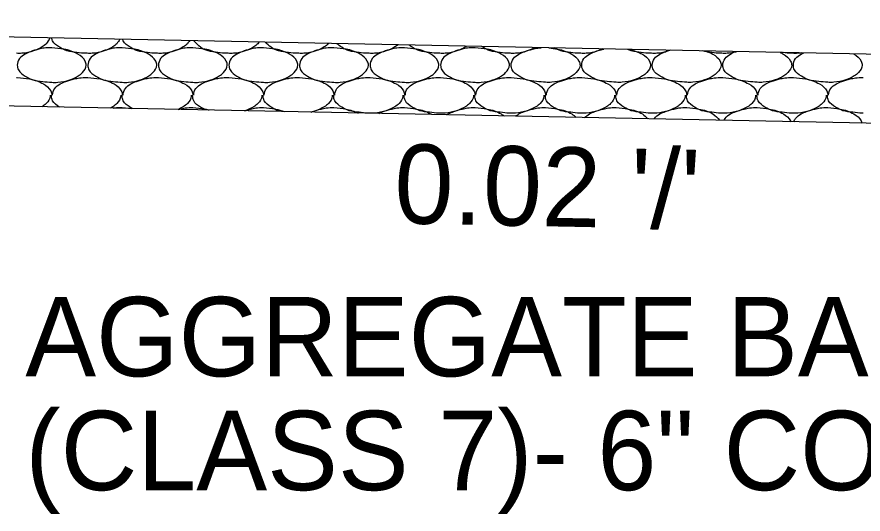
# Model space of a CAD drawing. Extents: x 1364961 to 1365294, y 367927 to 368034.
# Drawn here: x 1365039.35 to 1365045.49, y 367994.83 to 367998.44 of the extents above; entities that cross this region are included whole.
import ezdxf

# ---------------------------------------------------------------- set-up
doc = ezdxf.new("R2010")
doc.units = 0
doc.layers.add('Default', color=7, linetype='Continuous')

msp = doc.modelspace()

# ---------------------------------------------------------------- linework, layer by layer
at = {"layer": 'Default'}
for p, q in [((1365055.9752, 367997.9597), (1365031.9883, 367998.4397)), ((1365039.3502, 367997.9997), (1365039.3562, 367997.9997)), ((1365039.8622, 367997.9997), (1365039.8682, 367997.9997)), ((1365040.3742, 367997.9997), (1365040.3802, 367997.9997)), ((1365040.8862, 367997.9997), (1365040.8922, 367997.9997)), ((1365041.3982, 367997.9997), (1365041.4042, 367997.9997)), ((1365041.9102, 367997.9997), (1365041.9162, 367997.9997)), ((1365042.4222, 367997.9997), (1365042.4282, 367997.9997)), ((1365042.9342, 367997.9997), (1365042.9402, 367997.9997)), ((1365043.4462, 367997.9997), (1365043.4522, 367997.9997)), ((1365043.9582, 367997.9997), (1365043.9642, 367997.9997)), ((1365044.4702, 367997.9997), (1365044.4762, 367997.9997)), ((1365044.9822, 367997.9997), (1365044.9882, 367997.9997)), ((1365055.9752, 367997.4597), (1365031.9783, 367997.9397)), ((1365040.1182, 367997.7817), (1365040.1862, 367997.7757))]:
    msp.add_line(p, q, dxfattribs=at)
for points in [[(1365039.5922, 367998.2877), (1365039.5662, 367998.2457), (1365039.5362, 367998.2217), (1365039.4742, 367998.1937), (1365039.3882, 367998.1757), (1365039.3502, 367998.1757)], [(1365039.8622, 367998.1757), (1365039.8542, 367998.1757), (1365039.7882, 367998.1817), (1365039.7162, 367998.1937), (1365039.6622, 367998.2197), (1365039.6122, 367998.2657), (1365039.6052, 367998.2877)], [(1365040.1002, 367998.2777), (1365040.0782, 367998.2457), (1365040.0482, 367998.2217), (1365039.9862, 367998.1937), (1365039.9002, 367998.1757), (1365039.8622, 367998.1757)], [(1365040.3742, 367998.1757), (1365040.3662, 367998.1757), (1365040.3002, 367998.1817), (1365040.2282, 367998.1937), (1365040.1742, 367998.2197), (1365040.1242, 367998.2657), (1365040.1192, 367998.2767)], [(1365040.6072, 367998.2677), (1365040.5902, 367998.2457), (1365040.5602, 367998.2217), (1365040.4982, 367998.1937), (1365040.4122, 367998.1757), (1365040.3742, 367998.1757)], [(1365040.8862, 367998.1757), (1365040.8782, 367998.1757), (1365040.8122, 367998.1817), (1365040.7402, 367998.1937), (1365040.6862, 367998.2197), (1365040.6362, 367998.2657), (1365040.6352, 367998.2667)], [(1365041.1122, 367998.2567), (1365041.1022, 367998.2457), (1365041.0722, 367998.2217), (1365041.0102, 367998.1937), (1365040.9242, 367998.1757), (1365040.8862, 367998.1757)], [(1365041.3982, 367998.1757), (1365041.3902, 367998.1757), (1365041.3242, 367998.1817), (1365041.2522, 367998.1937), (1365041.1982, 367998.2197), (1365041.1542, 367998.2567)], [(1365041.6152, 367998.2467), (1365041.6142, 367998.2457), (1365041.5842, 367998.2217), (1365041.5222, 367998.1937), (1365041.4362, 367998.1757), (1365041.3982, 367998.1757)], [(1365041.9102, 367998.1757), (1365041.9022, 367998.1757), (1365041.8362, 367998.1817), (1365041.7642, 367998.1937), (1365041.7102, 367998.2197), (1365041.6752, 367998.2457)], [(1365042.1172, 367998.2367), (1365042.0962, 367998.2217), (1365042.0342, 367998.1937), (1365041.9482, 367998.1757), (1365041.9102, 367998.1757)], [(1365039.6062, 367998.2157), (1365039.6942, 367998.2057), (1365039.7962, 367998.1697), (1365039.8482, 367998.1197), (1365039.8562, 367998.0897), (1365039.8282, 367998.0357), (1365039.7982, 367998.0117), (1365039.7362, 367997.9837), (1365039.6502, 367997.9657), (1365039.6062, 367997.9657), (1365039.5402, 367997.9717), (1365039.4682, 367997.9837), (1365039.4142, 367998.0097), (1365039.3642, 367998.0557), (1365039.3562, 367998.0897), (1365039.3722, 367998.1377), (1365039.4122, 367998.1697), (1365039.4522, 367998.1877), (1365039.5122, 367998.2057), (1365039.5502, 367998.2137), (1365039.6062, 367998.2157)], [(1365040.1182, 367998.2157), (1365040.2062, 367998.2057), (1365040.3082, 367998.1697), (1365040.3602, 367998.1197), (1365040.3682, 367998.0897), (1365040.3402, 367998.0357), (1365040.3102, 367998.0117), (1365040.2482, 367997.9837), (1365040.1622, 367997.9657), (1365040.1182, 367997.9657), (1365040.0522, 367997.9717), (1365039.9802, 367997.9837), (1365039.9262, 367998.0097), (1365039.8762, 367998.0557), (1365039.8682, 367998.0897), (1365039.8842, 367998.1377), (1365039.9242, 367998.1697), (1365039.9642, 367998.1877), (1365040.0242, 367998.2057), (1365040.0622, 367998.2137), (1365040.1182, 367998.2157)], [(1365040.6302, 367998.2157), (1365040.7182, 367998.2057), (1365040.8202, 367998.1697), (1365040.8722, 367998.1197), (1365040.8802, 367998.0897), (1365040.8522, 367998.0357), (1365040.8222, 367998.0117), (1365040.7602, 367997.9837), (1365040.6742, 367997.9657), (1365040.6302, 367997.9657), (1365040.5642, 367997.9717), (1365040.4922, 367997.9837), (1365040.4382, 367998.0097), (1365040.3882, 367998.0557), (1365040.3802, 367998.0897), (1365040.3962, 367998.1377), (1365040.4362, 367998.1697), (1365040.4762, 367998.1877), (1365040.5362, 367998.2057), (1365040.5742, 367998.2137), (1365040.6302, 367998.2157)], [(1365041.1422, 367998.2157), (1365041.2302, 367998.2057), (1365041.3322, 367998.1697), (1365041.3842, 367998.1197), (1365041.3922, 367998.0897), (1365041.3642, 367998.0357), (1365041.3342, 367998.0117), (1365041.2722, 367997.9837), (1365041.1862, 367997.9657), (1365041.1422, 367997.9657), (1365041.0762, 367997.9717), (1365041.0042, 367997.9837), (1365040.9502, 367998.0097), (1365040.9002, 367998.0557), (1365040.8922, 367998.0897), (1365040.9082, 367998.1377), (1365040.9482, 367998.1697), (1365040.9882, 367998.1877), (1365041.0482, 367998.2057), (1365041.0862, 367998.2137), (1365041.1422, 367998.2157)], [(1365041.6542, 367998.2157), (1365041.7422, 367998.2057), (1365041.8442, 367998.1697), (1365041.8962, 367998.1197), (1365041.9042, 367998.0897), (1365041.8762, 367998.0357), (1365041.8462, 367998.0117), (1365041.7842, 367997.9837), (1365041.6982, 367997.9657), (1365041.6542, 367997.9657), (1365041.5882, 367997.9717), (1365041.5162, 367997.9837), (1365041.4622, 367998.0097), (1365041.4122, 367998.0557), (1365041.4042, 367998.0897), (1365041.4202, 367998.1377), (1365041.4602, 367998.1697), (1365041.5002, 367998.1877), (1365041.5602, 367998.2057), (1365041.5982, 367998.2137), (1365041.6542, 367998.2157)], [(1365042.1662, 367998.2157), (1365042.2542, 367998.2057), (1365042.3562, 367998.1697), (1365042.4082, 367998.1197), (1365042.4162, 367998.0897), (1365042.3882, 367998.0357), (1365042.3582, 367998.0117), (1365042.2962, 367997.9837), (1365042.2102, 367997.9657), (1365042.1662, 367997.9657), (1365042.1002, 367997.9717), (1365042.0282, 367997.9837), (1365041.9742, 367998.0097), (1365041.9242, 367998.0557), (1365041.9162, 367998.0897), (1365041.9322, 367998.1377), (1365041.9722, 367998.1697), (1365042.0122, 367998.1877), (1365042.0722, 367998.2057), (1365042.1102, 367998.2137), (1365042.1662, 367998.2157)], [(1365042.4222, 367998.1757), (1365042.4142, 367998.1757), (1365042.3482, 367998.1817), (1365042.2762, 367998.1937), (1365042.2222, 367998.2197), (1365042.1992, 367998.2357)], [(1365042.6172, 367998.2267), (1365042.6082, 367998.2217), (1365042.5462, 367998.1937), (1365042.4602, 367998.1757), (1365042.4222, 367998.1757)], [(1365042.6782, 367998.2157), (1365042.7662, 367998.2057), (1365042.8682, 367998.1697), (1365042.9202, 367998.1197), (1365042.9282, 367998.0897), (1365042.9002, 367998.0357), (1365042.8702, 367998.0117), (1365042.8082, 367997.9837), (1365042.7222, 367997.9657), (1365042.6782, 367997.9657), (1365042.6122, 367997.9717), (1365042.5402, 367997.9837), (1365042.4862, 367998.0097), (1365042.4362, 367998.0557), (1365042.4282, 367998.0897), (1365042.4442, 367998.1377), (1365042.4842, 367998.1697), (1365042.5242, 367998.1877), (1365042.5842, 367998.2057), (1365042.6222, 367998.2137), (1365042.6782, 367998.2157)], [(1365042.9342, 367998.1757), (1365042.9262, 367998.1757), (1365042.8602, 367998.1817), (1365042.7882, 367998.1937), (1365042.7342, 367998.2197), (1365042.7262, 367998.2247)], [(1365043.1122, 367998.2167), (1365043.0582, 367998.1937), (1365042.9722, 367998.1757), (1365042.9342, 367998.1757)], [(1365043.2132, 367998.2147), (1365043.2782, 367998.2057), (1365043.3802, 367998.1697), (1365043.4322, 367998.1197), (1365043.4402, 367998.0897), (1365043.4122, 367998.0357), (1365043.3822, 367998.0117), (1365043.3202, 367997.9837), (1365043.2342, 367997.9657), (1365043.1902, 367997.9657), (1365043.1242, 367997.9717), (1365043.0522, 367997.9837), (1365042.9982, 367998.0097), (1365042.9482, 367998.0557), (1365042.9402, 367998.0897), (1365042.9562, 367998.1377), (1365042.9962, 367998.1697), (1365043.0362, 367998.1877), (1365043.0962, 367998.2057), (1365043.1342, 367998.2137), (1365043.1582, 367998.2157)], [(1365043.4462, 367998.1757), (1365043.4382, 367998.1757), (1365043.3722, 367998.1817), (1365043.3002, 367998.1937), (1365043.2552, 367998.2147)], [(1365043.6042, 367998.2077), (1365043.5702, 367998.1937), (1365043.4842, 367998.1757), (1365043.4462, 367998.1757)], [(1365043.8012, 367998.2037), (1365043.8922, 367998.1697), (1365043.9442, 367998.1197), (1365043.9522, 367998.0897), (1365043.9242, 367998.0357), (1365043.8942, 367998.0117), (1365043.8322, 367997.9837), (1365043.7462, 367997.9657), (1365043.7022, 367997.9657), (1365043.6362, 367997.9717), (1365043.5642, 367997.9837), (1365043.5102, 367998.0097), (1365043.4602, 367998.0557), (1365043.4522, 367998.0897), (1365043.4682, 367998.1377), (1365043.5082, 367998.1697), (1365043.5482, 367998.1877), (1365043.6082, 367998.2057), (1365043.6132, 367998.2067)], [(1365043.9582, 367998.1757), (1365043.9502, 367998.1757), (1365043.8842, 367998.1817), (1365043.8122, 367998.1937), (1365043.7862, 367998.2037)], [(1365044.0932, 367998.1977), (1365044.0822, 367998.1937), (1365043.9962, 367998.1757), (1365043.9582, 367998.1757)], [(1365044.3522, 367998.1927), (1365044.4042, 367998.1697), (1365044.4562, 367998.1197), (1365044.4642, 367998.0897), (1365044.4362, 367998.0357), (1365044.4062, 367998.0117), (1365044.3442, 367997.9837), (1365044.2582, 367997.9657), (1365044.2142, 367997.9657), (1365044.1482, 367997.9717), (1365044.0762, 367997.9837), (1365044.0222, 367998.0097), (1365043.9722, 367998.0557), (1365043.9642, 367998.0897), (1365043.9802, 367998.1377), (1365044.0202, 367998.1697), (1365044.0602, 367998.1877), (1365044.0912, 367998.1977)], [(1365044.4702, 367998.1757), (1365044.4622, 367998.1757), (1365044.3962, 367998.1817), (1365044.3282, 367998.1927)], [(1365044.5752, 367998.1877), (1365044.5082, 367998.1757), (1365044.4702, 367998.1757)], [(1365044.8922, 367998.1817), (1365044.9162, 367998.1697), (1365044.9682, 367998.1197), (1365044.9762, 367998.0897), (1365044.9482, 367998.0357), (1365044.9182, 367998.0117), (1365044.8562, 367997.9837), (1365044.7702, 367997.9657), (1365044.7262, 367997.9657), (1365044.6602, 367997.9717), (1365044.5882, 367997.9837), (1365044.5342, 367998.0097), (1365044.4842, 367998.0557), (1365044.4762, 367998.0897), (1365044.4922, 367998.1377), (1365044.5322, 367998.1697), (1365044.5722, 367998.1877), (1365044.5732, 367998.1877)], [(1365044.9822, 367998.1757), (1365044.9742, 367998.1757), (1365044.9142, 367998.1807)], [(1365045.0462, 367998.1787), (1365045.0202, 367998.1757), (1365044.9822, 367998.1757)], [(1365045.4262, 367998.1707), (1365045.4282, 367998.1697), (1365045.4802, 367998.1197), (1365045.4882, 367998.0897), (1365045.4602, 367998.0357), (1365045.4302, 367998.0117), (1365045.3682, 367997.9837), (1365045.2822, 367997.9657), (1365045.2382, 367997.9657), (1365045.1722, 367997.9717), (1365045.1002, 367997.9837), (1365045.0462, 367998.0097), (1365044.9962, 367998.0557), (1365044.9882, 367998.0897), (1365045.0042, 367998.1377), (1365045.0442, 367998.1697), (1365045.0612, 367998.1777)], [(1365039.3562, 367997.9997), (1365039.4442, 367997.9897), (1365039.5462, 367997.9537), (1365039.5982, 367997.9037), (1365039.6062, 367997.8737), (1365039.6062, 367997.8717)], [(1365039.6122, 367997.8717), (1365039.6122, 367997.8737), (1365039.6282, 367997.9217), (1365039.6682, 367997.9537), (1365039.7082, 367997.9717), (1365039.7682, 367997.9897), (1365039.8062, 367997.9977), (1365039.8622, 367997.9997)], [(1365039.8682, 367997.9997), (1365039.9562, 367997.9897), (1365040.0582, 367997.9537), (1365040.1102, 367997.9037), (1365040.1182, 367997.8737), (1365040.1182, 367997.8717)], [(1365040.1242, 367997.8717), (1365040.1242, 367997.8737), (1365040.1402, 367997.9217), (1365040.1802, 367997.9537), (1365040.2202, 367997.9717), (1365040.2802, 367997.9897), (1365040.3182, 367997.9977), (1365040.3742, 367997.9997)], [(1365040.3802, 367997.9997), (1365040.4682, 367997.9897), (1365040.5702, 367997.9537), (1365040.6222, 367997.9037), (1365040.6302, 367997.8737), (1365040.6302, 367997.8717)], [(1365040.6362, 367997.8717), (1365040.6362, 367997.8737), (1365040.6522, 367997.9217), (1365040.6922, 367997.9537), (1365040.7322, 367997.9717), (1365040.7922, 367997.9897), (1365040.8302, 367997.9977), (1365040.8862, 367997.9997)], [(1365040.8922, 367997.9997), (1365040.9802, 367997.9897), (1365041.0822, 367997.9537), (1365041.1342, 367997.9037), (1365041.1422, 367997.8737), (1365041.1422, 367997.8717)], [(1365041.1482, 367997.8717), (1365041.1482, 367997.8737), (1365041.1642, 367997.9217), (1365041.2042, 367997.9537), (1365041.2442, 367997.9717), (1365041.3042, 367997.9897), (1365041.3422, 367997.9977), (1365041.3982, 367997.9997)], [(1365041.4042, 367997.9997), (1365041.4922, 367997.9897), (1365041.5942, 367997.9537), (1365041.6462, 367997.9037), (1365041.6542, 367997.8737), (1365041.6542, 367997.8717)], [(1365041.6602, 367997.8717), (1365041.6602, 367997.8737), (1365041.6762, 367997.9217), (1365041.7162, 367997.9537), (1365041.7562, 367997.9717), (1365041.8162, 367997.9897), (1365041.8542, 367997.9977), (1365041.9102, 367997.9997)], [(1365041.9162, 367997.9997), (1365042.0042, 367997.9897), (1365042.1062, 367997.9537), (1365042.1582, 367997.9037), (1365042.1662, 367997.8737), (1365042.1662, 367997.8717)], [(1365042.1722, 367997.8717), (1365042.1722, 367997.8737), (1365042.1882, 367997.9217), (1365042.2282, 367997.9537), (1365042.2682, 367997.9717), (1365042.3282, 367997.9897), (1365042.3662, 367997.9977), (1365042.4222, 367997.9997)], [(1365042.4282, 367997.9997), (1365042.5162, 367997.9897), (1365042.6182, 367997.9537), (1365042.6702, 367997.9037), (1365042.6782, 367997.8737), (1365042.6782, 367997.8717)], [(1365042.6842, 367997.8717), (1365042.6842, 367997.8737), (1365042.7002, 367997.9217), (1365042.7402, 367997.9537), (1365042.7802, 367997.9717), (1365042.8402, 367997.9897), (1365042.8782, 367997.9977), (1365042.9342, 367997.9997)], [(1365042.9402, 367997.9997), (1365043.0282, 367997.9897), (1365043.1302, 367997.9537), (1365043.1822, 367997.9037), (1365043.1902, 367997.8737), (1365043.1902, 367997.8717)], [(1365043.1962, 367997.8717), (1365043.1962, 367997.8737), (1365043.2122, 367997.9217), (1365043.2522, 367997.9537), (1365043.2922, 367997.9717), (1365043.3522, 367997.9897), (1365043.3902, 367997.9977), (1365043.4462, 367997.9997)], [(1365043.4522, 367997.9997), (1365043.5402, 367997.9897), (1365043.6422, 367997.9537), (1365043.6942, 367997.9037), (1365043.7022, 367997.8737), (1365043.7022, 367997.8717)], [(1365043.7082, 367997.8717), (1365043.7082, 367997.8737), (1365043.7242, 367997.9217), (1365043.7642, 367997.9537), (1365043.8042, 367997.9717), (1365043.8642, 367997.9897), (1365043.9022, 367997.9977), (1365043.9582, 367997.9997)], [(1365043.9642, 367997.9997), (1365044.0522, 367997.9897), (1365044.1542, 367997.9537), (1365044.2062, 367997.9037), (1365044.2142, 367997.8737), (1365044.2142, 367997.8717)], [(1365044.2202, 367997.8717), (1365044.2202, 367997.8737), (1365044.2362, 367997.9217), (1365044.2762, 367997.9537), (1365044.3162, 367997.9717), (1365044.3762, 367997.9897), (1365044.4142, 367997.9977), (1365044.4702, 367997.9997)], [(1365044.4762, 367997.9997), (1365044.5642, 367997.9897), (1365044.6662, 367997.9537), (1365044.7182, 367997.9037), (1365044.7262, 367997.8737), (1365044.7262, 367997.8717)], [(1365044.7322, 367997.8717), (1365044.7322, 367997.8737), (1365044.7482, 367997.9217), (1365044.7882, 367997.9537), (1365044.8282, 367997.9717), (1365044.8882, 367997.9897), (1365044.9262, 367997.9977), (1365044.9822, 367997.9997)], [(1365044.9882, 367997.9997), (1365045.0762, 367997.9897), (1365045.1782, 367997.9537), (1365045.2302, 367997.9037), (1365045.2382, 367997.8737), (1365045.2382, 367997.8717)], [(1365045.2442, 367997.8717), (1365045.2442, 367997.8737), (1365045.2602, 367997.9217), (1365045.3002, 367997.9537), (1365045.3402, 367997.9717), (1365045.4002, 367997.9897), (1365045.4382, 367997.9977), (1365045.4942, 367997.9997)], [(1365039.5942, 367997.8717), (1365039.5942, 367997.8657), (1365039.5662, 367997.8117), (1365039.5372, 367997.7887)], [(1365039.6622, 367997.7857), (1365039.6122, 367997.8317), (1365039.6042, 367997.8657), (1365039.6042, 367997.8717)], [(1365040.1062, 367997.8717), (1365040.1062, 367997.8657), (1365040.0782, 367997.8117), (1365040.0482, 367997.7877), (1365040.0312, 367997.7787)], [(1365040.1912, 367997.7757), (1365040.1742, 367997.7857), (1365040.1242, 367997.8317), (1365040.1162, 367997.8657), (1365040.1162, 367997.8717)], [(1365040.6182, 367997.8717), (1365040.6182, 367997.8657), (1365040.5902, 367997.8117), (1365040.5602, 367997.7877), (1365040.5222, 367997.7687)], [(1365040.7242, 367997.7647), (1365040.6862, 367997.7857), (1365040.6362, 367997.8317), (1365040.6282, 367997.8657), (1365040.6282, 367997.8717)], [(1365041.1302, 367997.8717), (1365041.1302, 367997.8657), (1365041.1022, 367997.8117), (1365041.0722, 367997.7877), (1365041.0102, 367997.7597), (1365041.0082, 367997.7587)], [(1365041.2822, 367997.7537), (1365041.2522, 367997.7597), (1365041.1982, 367997.7857), (1365041.1482, 367997.8317), (1365041.1402, 367997.8657), (1365041.1402, 367997.8717)], [(1365041.6422, 367997.8717), (1365041.6422, 367997.8657), (1365041.6142, 367997.8117), (1365041.5842, 367997.7877), (1365041.5222, 367997.7597), (1365041.4872, 367997.7497)], [(1365041.9102, 367997.7417), (1365041.9022, 367997.7417), (1365041.8362, 367997.7477), (1365041.7642, 367997.7597), (1365041.7102, 367997.7857), (1365041.6602, 367997.8317), (1365041.6522, 367997.8657), (1365041.6522, 367997.8717)], [(1365042.1542, 367997.8717), (1365042.1542, 367997.8657), (1365042.1262, 367997.8117), (1365042.0962, 367997.7877), (1365042.0342, 367997.7597), (1365041.9482, 367997.7417), (1365041.9102, 367997.7417)], [(1365042.4222, 367997.7417), (1365042.4142, 367997.7417), (1365042.3482, 367997.7477), (1365042.2762, 367997.7597), (1365042.2222, 367997.7857), (1365042.1722, 367997.8317), (1365042.1642, 367997.8657), (1365042.1642, 367997.8717)], [(1365042.6662, 367997.8717), (1365042.6662, 367997.8657), (1365042.6382, 367997.8117), (1365042.6082, 367997.7877), (1365042.5462, 367997.7597), (1365042.4602, 367997.7417), (1365042.4222, 367997.7417)], [(1365042.9342, 367997.7417), (1365042.9262, 367997.7417), (1365042.8602, 367997.7477), (1365042.7882, 367997.7597), (1365042.7342, 367997.7857), (1365042.6842, 367997.8317), (1365042.6762, 367997.8657), (1365042.6762, 367997.8717)], [(1365043.1782, 367997.8717), (1365043.1782, 367997.8657), (1365043.1502, 367997.8117), (1365043.1202, 367997.7877), (1365043.0582, 367997.7597), (1365042.9722, 367997.7417), (1365042.9342, 367997.7417)], [(1365043.4462, 367997.7417), (1365043.4382, 367997.7417), (1365043.3722, 367997.7477), (1365043.3002, 367997.7597), (1365043.2462, 367997.7857), (1365043.1962, 367997.8317), (1365043.1882, 367997.8657), (1365043.1882, 367997.8717)], [(1365043.6902, 367997.8717), (1365043.6902, 367997.8657), (1365043.6622, 367997.8117), (1365043.6322, 367997.7877), (1365043.5702, 367997.7597), (1365043.4842, 367997.7417), (1365043.4462, 367997.7417)], [(1365043.9582, 367997.7417), (1365043.9502, 367997.7417), (1365043.8842, 367997.7477), (1365043.8122, 367997.7597), (1365043.7582, 367997.7857), (1365043.7082, 367997.8317), (1365043.7002, 367997.8657), (1365043.7002, 367997.8717)], [(1365044.2022, 367997.8717), (1365044.2022, 367997.8657), (1365044.1742, 367997.8117), (1365044.1442, 367997.7877), (1365044.0822, 367997.7597), (1365043.9962, 367997.7417), (1365043.9582, 367997.7417)], [(1365044.4702, 367997.7417), (1365044.4622, 367997.7417), (1365044.3962, 367997.7477), (1365044.3242, 367997.7597), (1365044.2702, 367997.7857), (1365044.2202, 367997.8317), (1365044.2122, 367997.8657), (1365044.2122, 367997.8717)], [(1365044.7142, 367997.8717), (1365044.7142, 367997.8657), (1365044.6862, 367997.8117), (1365044.6562, 367997.7877), (1365044.5942, 367997.7597), (1365044.5082, 367997.7417), (1365044.4702, 367997.7417)], [(1365044.9822, 367997.7417), (1365044.9742, 367997.7417), (1365044.9082, 367997.7477), (1365044.8362, 367997.7597), (1365044.7822, 367997.7857), (1365044.7322, 367997.8317), (1365044.7242, 367997.8657), (1365044.7242, 367997.8717)], [(1365045.2262, 367997.8717), (1365045.2262, 367997.8657), (1365045.1982, 367997.8117), (1365045.1682, 367997.7877), (1365045.1062, 367997.7597), (1365045.0202, 367997.7417), (1365044.9822, 367997.7417)], [(1365045.4942, 367997.7417), (1365045.4862, 367997.7417), (1365045.4202, 367997.7477), (1365045.3482, 367997.7597), (1365045.2942, 367997.7857), (1365045.2442, 367997.8317), (1365045.2362, 367997.8657), (1365045.2362, 367997.8717)], [(1365040.0532, 367997.7777), (1365040.0622, 367997.7797), (1365040.1182, 367997.7817)], [(1365040.5252, 367997.7687), (1365040.5362, 367997.7717), (1365040.5742, 367997.7797), (1365040.6302, 367997.7817)], [(1365040.6302, 367997.7817), (1365040.7182, 367997.7717), (1365040.7492, 367997.7647)], [(1365041.0052, 367997.7587), (1365041.0482, 367997.7717), (1365041.0862, 367997.7797), (1365041.1422, 367997.7817)], [(1365041.1422, 367997.7817), (1365041.2302, 367997.7717), (1365041.2942, 367997.7537)], [(1365041.4892, 367997.7497), (1365041.5002, 367997.7537), (1365041.5602, 367997.7717), (1365041.5982, 367997.7797), (1365041.6542, 367997.7817)], [(1365041.6542, 367997.7817), (1365041.7422, 367997.7717), (1365041.8302, 367997.7427)], [(1365041.9802, 367997.7397), (1365042.0122, 367997.7537), (1365042.0722, 367997.7717), (1365042.1102, 367997.7797), (1365042.1662, 367997.7817)], [(1365042.1662, 367997.7817), (1365042.2542, 367997.7717), (1365042.3562, 367997.7357), (1365042.3622, 367997.7317)], [(1365042.4732, 367997.7297), (1365042.4842, 367997.7357), (1365042.5242, 367997.7537), (1365042.5842, 367997.7717), (1365042.6222, 367997.7797), (1365042.6782, 367997.7817)], [(1365042.6782, 367997.7817), (1365042.7662, 367997.7717), (1365042.8682, 367997.7357), (1365042.8892, 367997.7217)], [(1365042.9712, 367997.7197), (1365042.9962, 367997.7357), (1365043.0362, 367997.7537), (1365043.0962, 367997.7717), (1365043.1342, 367997.7797), (1365043.1902, 367997.7817)], [(1365043.1902, 367997.7817), (1365043.2782, 367997.7717), (1365043.3802, 367997.7357), (1365043.4122, 367997.7107)], [(1365043.4732, 367997.7097), (1365043.5082, 367997.7357), (1365043.5482, 367997.7537), (1365043.6082, 367997.7717), (1365043.6462, 367997.7797), (1365043.7022, 367997.7817)], [(1365043.7022, 367997.7817), (1365043.7902, 367997.7717), (1365043.8922, 367997.7357), (1365043.9332, 367997.7007)], [(1365043.9772, 367997.6997), (1365043.9802, 367997.7037), (1365044.0202, 367997.7357), (1365044.0602, 367997.7537), (1365044.1202, 367997.7717), (1365044.1582, 367997.7797), (1365044.2142, 367997.7817)], [(1365044.2142, 367997.7817), (1365044.3022, 367997.7717), (1365044.4042, 367997.7357), (1365044.4532, 367997.6897)], [(1365044.4842, 367997.6897), (1365044.4922, 367997.7037), (1365044.5322, 367997.7357), (1365044.5722, 367997.7537), (1365044.6322, 367997.7717), (1365044.6702, 367997.7797), (1365044.7262, 367997.7817)], [(1365044.7262, 367997.7817), (1365044.8142, 367997.7717), (1365044.9162, 367997.7357), (1365044.9682, 367997.6857), (1365044.9712, 367997.6797)], [(1365044.9922, 367997.6797), (1365045.0042, 367997.7037), (1365045.0442, 367997.7357), (1365045.0842, 367997.7537), (1365045.1442, 367997.7717), (1365045.1822, 367997.7797), (1365045.2382, 367997.7817)], [(1365045.2382, 367997.7817), (1365045.3262, 367997.7717), (1365045.4282, 367997.7357), (1365045.4802, 367997.6857), (1365045.4872, 367997.6697)]]:
    msp.add_spline(points, degree=3, dxfattribs=at)

# ---------------------------------------------------------------- texts
msp.add_text("0.02 '/'", height=0.576, rotation=358.85371, dxfattribs=at).set_placement((1365042.088, 367996.9433))
for s, p in [('AGGREGATE BASE COURSE', (1365039.4142, 367995.8326)), ('(CLASS 7)- 6" COMP\'D. DEPTH', (1365039.4142, 367995.0066))]:
    msp.add_text(s, height=0.576, dxfattribs=at).set_placement(p)

doc.saveas('drawing.dxf')
